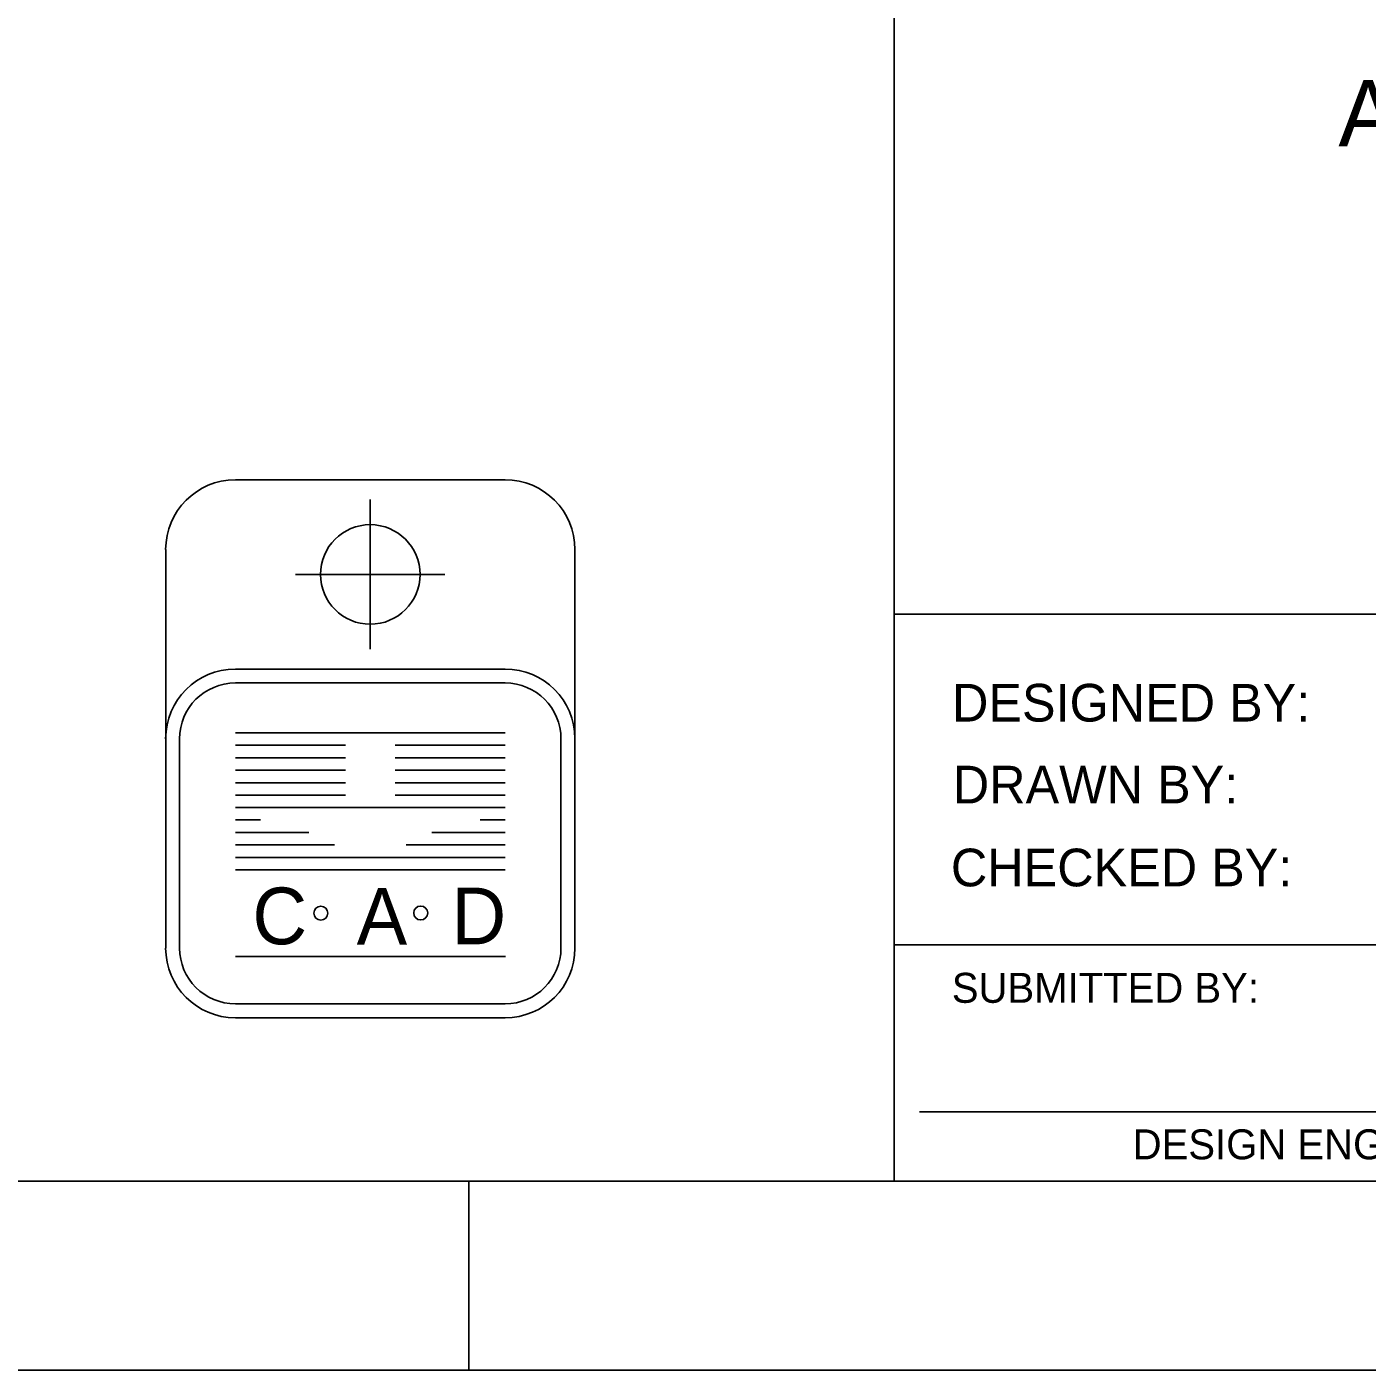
# Model space of a CAD drawing. Extents: x -0.2 to 13.5, y -0.2 to 9.5.
# Drawn here: x 10.235 to 11.417, y 0 to 1.184 of the extents above; entities that cross this region are included whole.
import ezdxf

# ---------------------------------------------------------------- set-up
doc = ezdxf.new("R2010")
doc.units = 0
doc.layers.add('Level 1', color=7, linetype='Continuous')
doc.layers.add('Level 2', color=7, linetype='Continuous')

msp = doc.modelspace()

# ---------------------------------------------------------------- linework, layer by layer
at = {"layer": 'Level 1'}
for p, q in [((11, 0.1667), (11, 1.75)), ((10.4191, 0.7851), (10.657, 0.7851)), ((10.538, 0.7676), (10.538, 0.6358)), ((10.3577, 0.3722), (10.3577, 0.7237)), ((10.7185, 0.3722), (10.7185, 0.7237)), ((10.4721, 0.7017), (10.6039, 0.7017)), ((13.1667, 0.6667), (11, 0.6667)), ((10.4191, 0.6182), (10.657, 0.6182)), ((10.4191, 0.6059), (10.657, 0.6059)), ((10.3699, 0.3722), (10.3699, 0.5567)), ((10.4191, 0.562), (10.657, 0.562)), ((10.7062, 0.3722), (10.7062, 0.5567)), ((10.4191, 0.551), (10.5161, 0.551)), ((10.56, 0.551), (10.657, 0.551)), ((10.4191, 0.54), (10.5161, 0.54)), ((10.56, 0.54), (10.657, 0.54)), ((10.4191, 0.529), (10.5161, 0.529)), ((10.56, 0.529), (10.657, 0.529)), ((10.4191, 0.518), (10.5161, 0.518)), ((10.56, 0.518), (10.657, 0.518)), ((10.4191, 0.507), (10.5161, 0.507)), ((10.56, 0.507), (10.657, 0.507)), ((10.4191, 0.496), (10.657, 0.496)), ((10.4191, 0.4851), (10.4411, 0.4851)), ((10.4191, 0.4741), (10.484, 0.4741)), ((10.6569, 0.4741), (10.5922, 0.4741)), ((10.6569, 0.4851), (10.635, 0.4851)), ((10.4191, 0.4631), (10.5065, 0.4631)), ((10.6569, 0.4631), (10.5696, 0.4631)), ((10.4191, 0.4521), (10.657, 0.4521)), ((10.4191, 0.4412), (10.657, 0.4412)), ((11, 0.375), (11.75, 0.375)), ((10.4191, 0.3648), (10.6574, 0.3648)), ((10.4191, 0.3229), (10.657, 0.3229)), ((10.4191, 0.3107), (10.657, 0.3107)), ((11.0224, 0.2278), (11.7234, 0.2278)), ((10.625, 0.1667), (10.625, 0))]:
    msp.add_line(p, q, dxfattribs=at)
for points in [[(0, 9.3333), (13.3333, 9.3333), (13.3333, 0), (0, 0)], [(0.5, 9.1667), (13.1667, 9.1667), (13.1667, 0.1667), (0.5, 0.1667)]]:
    msp.add_lwpolyline(points, close=True, dxfattribs=at)
for centre, radius in [((10.538, 0.7016), 0.0439), ((10.4944, 0.403), 0.00615), ((10.5825, 0.4031), 0.00615)]:
    msp.add_circle(centre, radius, dxfattribs=at)
for centre, radius, start, end in [((10.4191, 0.7236), 0.0615, 90, 180), ((10.657, 0.7236), 0.0615, 0, 90), ((10.4191, 0.5567), 0.0615, 90, 180), ((10.657, 0.5567), 0.0615, 0, 90), ((10.4191, 0.5567), 0.0492, 90, 180), ((10.657, 0.5567), 0.0492, 0, 90), ((10.4191, 0.3722), 0.0615, 180, 270), ((10.4191, 0.3722), 0.0492, 180, 270), ((10.657, 0.3722), 0.0615, 270, 360), ((10.657, 0.3722), 0.0492, 270, 360)]:
    msp.add_arc(centre, radius, start, end, dxfattribs=at)

# ---------------------------------------------------------------- texts
for s, height, p in [('DESIGNED BY:', 0.033208, (11.051, 0.5719)), ('DRAWN BY:', 0.03321, (11.0517, 0.4997)), ('CHECKED BY:', 0.033208, (11.05, 0.4266)), ('C', 0.05, (10.4341, 0.3755)), ('A', 0.05, (10.526, 0.3751)), ('D', 0.05, (10.6096, 0.3755)), ('SUBMITTED BY:', 0.026417, (11.0508, 0.3239)), ('DESIGN ENGINEER', 0.026417, (11.2103, 0.1859))]:
    msp.add_text(s, height=height, dxfattribs=at).set_placement(p)
at = {"layer": 'Level 2'}
msp.add_text('AND HWY. 45 LEVEE CLOSURES', height=0.058417, dxfattribs=at).set_placement((11.3917, 1.0791))

doc.saveas('drawing.dxf')
